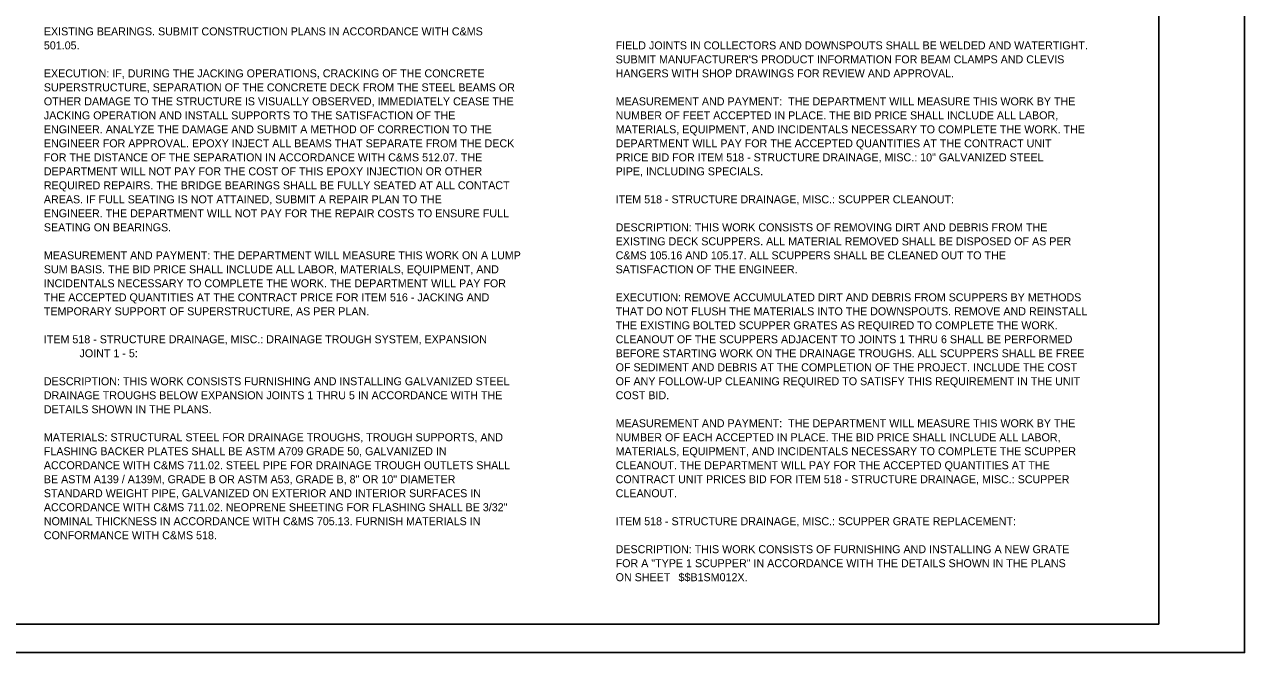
# Model space of a CAD drawing. Extents: x 0 to 72, y -26 to 50.
# Drawn here: x 50.66 to 72, y 26 to 37 of the extents above; entities that cross this region are included whole.
import ezdxf

# ---------------------------------------------------------------- set-up
doc = ezdxf.new("R2010")
doc.units = 0
doc.layers.add('SH_Cut_Line', color=7, linetype='Continuous')
doc.layers.add('SH_Data', color=7, linetype='Continuous')

msp = doc.modelspace()

# ---------------------------------------------------------------- linework, layer by layer
at = {"layer": 'SH_Cut_Line'}
for points in [[(38, 48), (72, 48), (72, 26), (38, 26)], [(40, 47.5), (70.5, 47.5), (70.5, 26.5), (40, 26.5)]]:
    msp.add_lwpolyline(points, close=True, dxfattribs=at)

# ---------------------------------------------------------------- texts
at = {"layer": 'SH_Data'}
for s, p in [('EXISTING BEARINGS. SUBMIT CONSTRUCTION PLANS IN ACCORDANCE WITH C&MS ', (51, 36.805)), ('501.05.', (51, 36.56)), ('FIELD JOINTS IN COLLECTORS AND DOWNSPOUTS SHALL BE WELDED AND WATERTIGHT. ', (61, 36.56)), ("SUBMIT MANUFACTURER'S PRODUCT INFORMATION FOR BEAM CLAMPS AND CLEVIS ", (61, 36.315)), ('EXECUTION: IF, DURING THE JACKING OPERATIONS, CRACKING OF THE CONCRETE ', (51, 36.07)), ('HANGERS WITH SHOP DRAWINGS FOR REVIEW AND APPROVAL. ', (61, 36.07)), ('SUPERSTRUCTURE, SEPARATION OF THE CONCRETE DECK FROM THE STEEL BEAMS OR ', (51, 35.825)), ('OTHER DAMAGE TO THE STRUCTURE IS VISUALLY OBSERVED, IMMEDIATELY CEASE THE ', (51, 35.58)), ('MEASUREMENT AND PAYMENT:  THE DEPARTMENT WILL MEASURE THIS WORK BY THE ', (61, 35.58)), ('JACKING OPERATION AND INSTALL SUPPORTS TO THE SATISFACTION OF THE ', (51, 35.335)), ('NUMBER OF FEET ACCEPTED IN PLACE. THE BID PRICE SHALL INCLUDE ALL LABOR, ', (61, 35.335)), ('ENGINEER. ANALYZE THE DAMAGE AND SUBMIT A METHOD OF CORRECTION TO THE ', (51, 35.09)), ('MATERIALS, EQUIPMENT, AND INCIDENTALS NECESSARY TO COMPLETE THE WORK. THE ', (61, 35.09)), ('ENGINEER FOR APPROVAL. EPOXY INJECT ALL BEAMS THAT SEPARATE FROM THE DECK ', (51, 34.845)), ('DEPARTMENT WILL PAY FOR THE ACCEPTED QUANTITIES AT THE CONTRACT UNIT ', (61, 34.845)), ('FOR THE DISTANCE OF THE SEPARATION IN ACCORDANCE WITH C&MS 512.07. THE ', (51, 34.6)), ('PRICE BID FOR ITEM 518 - STRUCTURE DRAINAGE, MISC.: 10" GALVANIZED STEEL ', (61, 34.6)), ('DEPARTMENT WILL NOT PAY FOR THE COST OF THIS EPOXY INJECTION OR OTHER ', (51, 34.355)), ('PIPE, INCLUDING SPECIALS.', (61, 34.355)), ('REQUIRED REPAIRS. THE BRIDGE BEARINGS SHALL BE FULLY SEATED AT ALL CONTACT ', (51, 34.11)), ('AREAS. IF FULL SEATING IS NOT ATTAINED, SUBMIT A REPAIR PLAN TO THE ', (51, 33.865)), ('ITEM 518 - STRUCTURE DRAINAGE, MISC.: SCUPPER CLEANOUT:', (61, 33.865)), ('ITEM 518 - STRUCTURE DRAINAGE, MISC.: SCUPPER CLEANOUT:', (61, 33.865)), ('ENGINEER. THE DEPARTMENT WILL NOT PAY FOR THE REPAIR COSTS TO ENSURE FULL ', (51, 33.62)), ('SEATING ON BEARINGS.', (51, 33.375)), ('DESCRIPTION: THIS WORK CONSISTS OF REMOVING DIRT AND DEBRIS FROM THE ', (61, 33.375)), ('EXISTING DECK SCUPPERS. ALL MATERIAL REMOVED SHALL BE DISPOSED OF AS PER ', (61, 33.13)), ('MEASUREMENT AND PAYMENT: THE DEPARTMENT WILL MEASURE THIS WORK ON A LUMP ', (51, 32.885)), ('C&MS 105.16 AND 105.17. ALL SCUPPERS SHALL BE CLEANED OUT TO THE ', (61, 32.885)), ('SUM BASIS. THE BID PRICE SHALL INCLUDE ALL LABOR, MATERIALS, EQUIPMENT, AND ', (51, 32.64)), ('SATISFACTION OF THE ENGINEER. ', (61, 32.64)), ('INCIDENTALS NECESSARY TO COMPLETE THE WORK. THE DEPARTMENT WILL PAY FOR ', (51, 32.395)), ('THE ACCEPTED QUANTITIES AT THE CONTRACT PRICE FOR ITEM 516 - JACKING AND ', (51, 32.15)), ('EXECUTION: REMOVE ACCUMULATED DIRT AND DEBRIS FROM SCUPPERS BY METHODS ', (61, 32.15)), ('TEMPORARY SUPPORT OF SUPERSTRUCTURE, AS PER PLAN.', (51, 31.905)), ('THAT DO NOT FLUSH THE MATERIALS INTO THE DOWNSPOUTS. REMOVE AND REINSTALL ', (61, 31.905)), ('THE EXISTING BOLTED SCUPPER GRATES AS REQUIRED TO COMPLETE THE WORK. ', (61, 31.66)), ('ITEM 518 - STRUCTURE DRAINAGE, MISC.: DRAINAGE TROUGH SYSTEM, EXPANSION', (51, 31.415)), ('ITEM 518 - STRUCTURE DRAINAGE, MISC.: DRAINAGE TROUGH SYSTEM, EXPANSION', (51, 31.415)), ('CLEANOUT OF THE SCUPPERS ADJACENT TO JOINTS 1 THRU 6 SHALL BE PERFORMED ', (61, 31.415)), ('            JOINT 1 - 5:', (51, 31.17)), ('            JOINT 1 - 5: ', (51, 31.17)), ('BEFORE STARTING WORK ON THE DRAINAGE TROUGHS. ALL SCUPPERS SHALL BE FREE ', (61, 31.17)), ('OF SEDIMENT AND DEBRIS AT THE COMPLETION OF THE PROJECT. INCLUDE THE COST ', (61, 30.925)), ('DESCRIPTION: THIS WORK CONSISTS FURNISHING AND INSTALLING GALVANIZED STEEL ', (51, 30.68)), ('OF ANY FOLLOW-UP CLEANING REQUIRED TO SATISFY THIS REQUIREMENT IN THE UNIT ', (61, 30.68)), ('DRAINAGE TROUGHS BELOW EXPANSION JOINTS 1 THRU 5 IN ACCORDANCE WITH THE ', (51, 30.435)), ('COST BID.       ', (61, 30.435)), ('DETAILS SHOWN IN THE PLANS.', (51, 30.19)), ('MEASUREMENT AND PAYMENT:  THE DEPARTMENT WILL MEASURE THIS WORK BY THE ', (61, 29.945)), ('MATERIALS: STRUCTURAL STEEL FOR DRAINAGE TROUGHS, TROUGH SUPPORTS, AND ', (51, 29.7)), ('NUMBER OF EACH ACCEPTED IN PLACE. THE BID PRICE SHALL INCLUDE ALL LABOR, ', (61, 29.7)), ('FLASHING BACKER PLATES SHALL BE ASTM A709 GRADE 50, GALVANIZED IN ', (51, 29.455)), ('MATERIALS, EQUIPMENT, AND INCIDENTALS NECESSARY TO COMPLETE THE SCUPPER ', (61, 29.455)), ('ACCORDANCE WITH C&MS 711.02. STEEL PIPE FOR DRAINAGE TROUGH OUTLETS SHALL ', (51, 29.21)), ('CLEANOUT. THE DEPARTMENT WILL PAY FOR THE ACCEPTED QUANTITIES AT THE ', (61, 29.21)), ('BE ASTM A139 / A139M, GRADE B OR ASTM A53, GRADE B, 8" OR 10" DIAMETER ', (51, 28.965)), ('CONTRACT UNIT PRICES BID FOR ITEM 518 - STRUCTURE DRAINAGE, MISC.: SCUPPER ', (61, 28.965)), ('STANDARD WEIGHT PIPE, GALVANIZED ON EXTERIOR AND INTERIOR SURFACES IN ', (51, 28.72)), ('CLEANOUT.', (61, 28.72)), ('ACCORDANCE WITH C&MS 711.02. NEOPRENE SHEETING FOR FLASHING SHALL BE 3/32" ', (51, 28.475)), ('NOMINAL THICKNESS IN ACCORDANCE WITH C&MS 705.13. FURNISH MATERIALS IN ', (51, 28.23)), ('ITEM 518 - STRUCTURE DRAINAGE, MISC.: SCUPPER GRATE REPLACEMENT:', (61, 28.23)), ('ITEM 518 - STRUCTURE DRAINAGE, MISC.: SCUPPER GRATE REPLACEMENT:', (61, 28.23)), ('CONFORMANCE WITH C&MS 518.', (51, 27.985)), ('DESCRIPTION: THIS WORK CONSISTS OF FURNISHING AND INSTALLING A NEW GRATE ', (61, 27.74)), ('FOR A "TYPE 1 SCUPPER" IN ACCORDANCE WITH THE DETAILS SHOWN IN THE PLANS', (61, 27.495)), ('ON SHEET', (61, 27.25)), ('$$B1SM012X.', (62.1, 27.25))]:
    msp.add_text(s, height=0.14, dxfattribs=at).set_placement(p)

doc.saveas('drawing.dxf')
